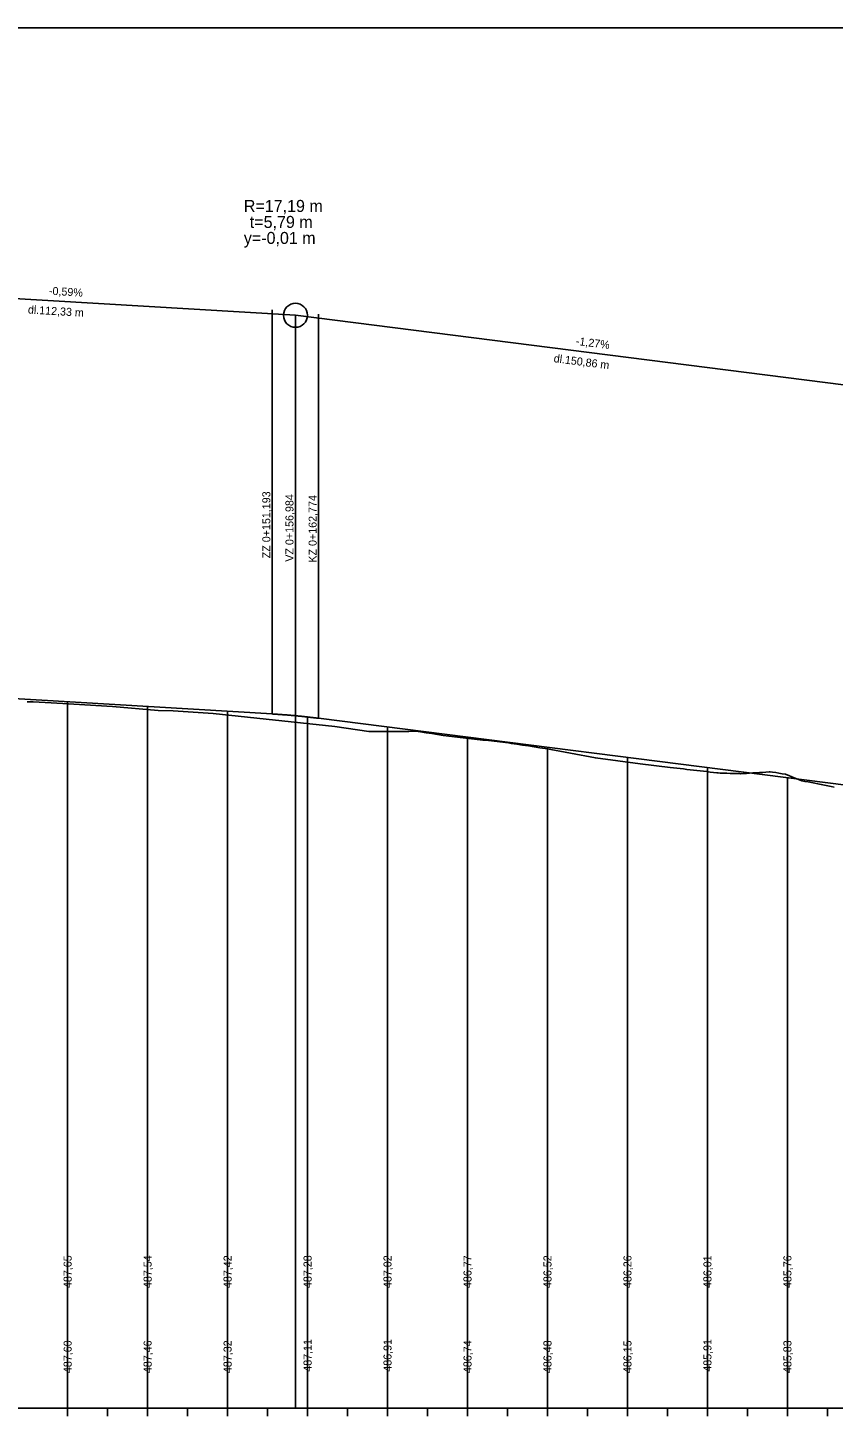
# Model space of a CAD drawing. Extents: x -632716 to -629545, y -1094726 to -1088285.
# Drawn here: x -632393.4 to -632192, y -1091019.7 to -1090670.2 of the extents above; entities that cross this region are included whole.
import ezdxf

# ---------------------------------------------------------------- set-up
doc = ezdxf.new("R2010")
doc.units = 0
for name, color, linetype in [('20', 7, 'Continuous'), ('Default', 7, 'Continuous'), ('formát', 7, 'Continuous'), ('NIVELETA_VYSKY', 7, 'Continuous'), ('REZ_TENKA', 7, 'Continuous'), ('REZ_TLUSTA', 7, 'Continuous'), ('SKLONY_NIVELETA', 7, 'Continuous'), ('SKLONY_POPIS', 7, 'Continuous'), ('TECNY_NIVELETA', 7, 'Continuous'), ('TEREN_VYSKY', 7, 'Continuous'), ('VOZOVKA', 7, 'Continuous')]:
    doc.layers.add(name, color=color, linetype=linetype)

msp = doc.modelspace()

# ---------------------------------------------------------------- linework, layer by layer
at = {"layer": '20'}
for points in [[(-632383.46, -1090838.65), (-632383.46, -1090965.2), (-632383.46, -1091015.2), (-632383.46, -1090955.2)], [(-632363.46, -1090839.84), (-632363.46, -1090965.2), (-632363.46, -1091015.2), (-632363.46, -1090955.2)], [(-632343.46, -1090841.03), (-632343.46, -1090965.2), (-632343.46, -1091015.2), (-632343.46, -1090955.2)], [(-632323.46, -1090842.44), (-632323.46, -1090965.2), (-632323.46, -1091015.2), (-632323.46, -1090955.2)], [(-632303.46, -1090844.95), (-632303.46, -1090965.2), (-632303.46, -1091015.2), (-632303.46, -1090955.2)], [(-632283.46, -1090847.49), (-632283.46, -1090965.2), (-632283.46, -1091015.2), (-632283.46, -1090955.2)], [(-632263.46, -1090850.03), (-632263.46, -1090965.2), (-632263.46, -1091015.2), (-632263.46, -1090955.2)], [(-632243.46, -1090852.56), (-632243.46, -1090965.2), (-632243.46, -1091015.2), (-632243.46, -1090955.2)], [(-632223.46, -1090855.1), (-632223.46, -1090965.2), (-632223.46, -1091015.2), (-632223.46, -1090955.2)], [(-632203.46, -1090857.64), (-632203.46, -1090965.2), (-632203.46, -1091015.2), (-632203.46, -1090955.2)]]:
    msp.add_lwpolyline(points, dxfattribs=at)
at = {"layer": 'Default'}
for p, q in [((-632412.05, -1090836.95), (-632332.27, -1090841.69)), ((-632412.05, -1090836.95), (-632332.27, -1090841.69)), ((-632320.69, -1090842.77), (-632188.1, -1090859.58)), ((-632320.69, -1090842.77), (-632188.1, -1090859.58))]:
    msp.add_line(p, q, dxfattribs=at)
msp.add_lwpolyline([(-632332.27, -1090841.69), (-632332.03, -1090841.71), (-632331.79, -1090841.72), (-632331.55, -1090841.74), (-632331.31, -1090841.75), (-632331.06, -1090841.77), (-632330.82, -1090841.78), (-632330.58, -1090841.8), (-632330.34, -1090841.82), (-632330.1, -1090841.83), (-632329.86, -1090841.85), (-632329.62, -1090841.87), (-632329.38, -1090841.89), (-632329.13, -1090841.91), (-632328.89, -1090841.92), (-632328.65, -1090841.94), (-632328.41, -1090841.96), (-632328.17, -1090841.98), (-632327.93, -1090842), (-632327.69, -1090842.02), (-632327.45, -1090842.05), (-632327.2, -1090842.07), (-632326.96, -1090842.09), (-632326.72, -1090842.11), (-632326.24, -1090842.15), (-632326, -1090842.18), (-632325.76, -1090842.2), (-632325.52, -1090842.22), (-632325.27, -1090842.25), (-632325.03, -1090842.27), (-632324.79, -1090842.3), (-632324.55, -1090842.32), (-632324.31, -1090842.35), (-632324.07, -1090842.37), (-632323.83, -1090842.4), (-632323.58, -1090842.43), (-632323.34, -1090842.45), (-632323.1, -1090842.48), (-632322.86, -1090842.51), (-632322.62, -1090842.54), (-632322.38, -1090842.56), (-632322.14, -1090842.59), (-632321.9, -1090842.62), (-632321.65, -1090842.65), (-632321.41, -1090842.68), (-632321.17, -1090842.71), (-632320.93, -1090842.74), (-632320.69, -1090842.77)], dxfattribs=at)
msp.add_lwpolyline([(-632332.27, -1090841.69), (-632332.03, -1090841.71), (-632331.79, -1090841.72), (-632331.55, -1090841.74), (-632331.31, -1090841.75), (-632331.06, -1090841.77), (-632330.82, -1090841.78), (-632330.58, -1090841.8), (-632330.34, -1090841.82), (-632330.1, -1090841.83), (-632329.86, -1090841.85), (-632329.62, -1090841.87), (-632329.38, -1090841.89), (-632329.13, -1090841.91), (-632328.89, -1090841.92), (-632328.65, -1090841.94), (-632328.41, -1090841.96), (-632328.17, -1090841.98), (-632327.93, -1090842), (-632327.69, -1090842.02), (-632327.45, -1090842.05), (-632327.2, -1090842.07), (-632326.96, -1090842.09), (-632326.72, -1090842.11), (-632326.24, -1090842.15), (-632326, -1090842.18), (-632325.76, -1090842.2), (-632325.52, -1090842.22), (-632325.27, -1090842.25), (-632325.03, -1090842.27), (-632324.79, -1090842.3), (-632324.55, -1090842.32), (-632324.31, -1090842.35), (-632324.07, -1090842.37), (-632323.83, -1090842.4), (-632323.58, -1090842.43), (-632323.34, -1090842.45), (-632323.1, -1090842.48), (-632322.86, -1090842.51), (-632322.62, -1090842.54), (-632322.38, -1090842.56), (-632322.14, -1090842.59), (-632321.9, -1090842.62), (-632321.65, -1090842.65), (-632321.41, -1090842.68), (-632321.17, -1090842.71), (-632320.93, -1090842.74), (-632320.69, -1090842.77)], dxfattribs=at)
at = {"layer": 'formát'}
msp.add_lwpolyline([(-632585.29, -1091264.2), (-630730.3, -1091264.2), (-630730.3, -1090670.2), (-632585.29, -1090670.2)], close=True, dxfattribs=at)
at = {"layer": 'REZ_TENKA'}
for p, q in [((-632373.46, -1091017.2), (-632373.46, -1091015.2)), ((-632363.46, -1091017.2), (-632363.46, -1091015.2)), ((-632353.46, -1091017.2), (-632353.46, -1091015.2)), ((-632343.46, -1091017.2), (-632343.46, -1091015.2)), ((-632333.46, -1091017.2), (-632333.46, -1091015.2)), ((-632323.46, -1091017.2), (-632323.46, -1091015.2)), ((-632313.46, -1091017.2), (-632313.46, -1091015.2)), ((-632303.46, -1091017.2), (-632303.46, -1091015.2)), ((-632293.46, -1091017.2), (-632293.46, -1091015.2)), ((-632273.46, -1091017.2), (-632273.46, -1091015.2)), ((-632263.46, -1091017.2), (-632263.46, -1091015.2)), ((-632253.46, -1091017.2), (-632253.46, -1091015.2)), ((-632243.46, -1091017.2), (-632243.46, -1091015.2)), ((-632233.46, -1091017.2), (-632233.46, -1091015.2)), ((-632223.46, -1091017.2), (-632223.46, -1091015.2)), ((-632213.46, -1091017.2), (-632213.46, -1091015.2)), ((-632203.46, -1091017.2), (-632203.46, -1091015.2)), ((-632193.46, -1091017.2), (-632193.46, -1091015.2))]:
    msp.add_line(p, q, dxfattribs=at)
at = {"layer": 'REZ_TLUSTA'}
for p, q in [((-632483.46, -1091015.2), (-630763.46, -1091015.2)), ((-632383.46, -1091017.2), (-632383.46, -1091013.2)), ((-632283.46, -1091017.2), (-632283.46, -1091013.2))]:
    msp.add_line(p, q, dxfattribs=at)
at = {"layer": 'SKLONY_NIVELETA'}
for p, q in [((-632438.81, -1090735.36), (-632326.48, -1090742.03)), ((-632326.48, -1090742.03), (-632326.48, -1091015.2)), ((-632326.48, -1090742.03), (-632175.62, -1090761.17)), ((-632412.05, -1090836.95), (-632332.27, -1090841.69)), ((-632320.69, -1090842.77), (-632188.1, -1090859.58))]:
    msp.add_line(p, q, dxfattribs=at)
msp.add_lwpolyline([(-632332.27, -1090841.69), (-632332.03, -1090841.71), (-632331.79, -1090841.72), (-632331.55, -1090841.74), (-632331.31, -1090841.75), (-632331.06, -1090841.77), (-632330.82, -1090841.78), (-632330.58, -1090841.8), (-632330.34, -1090841.82), (-632330.1, -1090841.83), (-632329.86, -1090841.85), (-632329.62, -1090841.87), (-632329.38, -1090841.89), (-632329.13, -1090841.91), (-632328.89, -1090841.92), (-632328.65, -1090841.94), (-632328.41, -1090841.96), (-632328.17, -1090841.98), (-632327.93, -1090842), (-632327.69, -1090842.02), (-632327.45, -1090842.05), (-632327.2, -1090842.07), (-632326.96, -1090842.09), (-632326.72, -1090842.11), (-632326.24, -1090842.15), (-632326, -1090842.18), (-632325.76, -1090842.2), (-632325.52, -1090842.22), (-632325.27, -1090842.25), (-632325.03, -1090842.27), (-632324.79, -1090842.3), (-632324.55, -1090842.32), (-632324.31, -1090842.35), (-632324.07, -1090842.37), (-632323.83, -1090842.4), (-632323.58, -1090842.43), (-632323.34, -1090842.45), (-632323.1, -1090842.48), (-632322.86, -1090842.51), (-632322.62, -1090842.54), (-632322.38, -1090842.56), (-632322.14, -1090842.59), (-632321.9, -1090842.62), (-632321.65, -1090842.65), (-632321.41, -1090842.68), (-632321.17, -1090842.71), (-632320.93, -1090842.74), (-632320.69, -1090842.77)], dxfattribs=at)
msp.add_circle((-632326.48, -1090742.03), 3, dxfattribs=at)
at = {"layer": 'TECNY_NIVELETA'}
for p, q in [((-632332.27, -1090841.69), (-632332.27, -1090740.69)), ((-632326.48, -1090742.03), (-632326.48, -1090742.03)), ((-632320.69, -1090842.77), (-632320.69, -1090741.77))]:
    msp.add_line(p, q, dxfattribs=at)
at = {"layer": 'VOZOVKA'}
msp.add_lwpolyline([(-632393.56, -1090838.66), (-632393.1, -1090838.65), (-632392.96, -1090838.65), (-632392.07, -1090838.69), (-632390.58, -1090838.77), (-632389.1, -1090838.86), (-632387.61, -1090838.94), (-632386.13, -1090839.02), (-632384.64, -1090839.1), (-632372.22, -1090839.79), (-632360.82, -1090840.81), (-632357.08, -1090840.92), (-632347.06, -1090841.56), (-632316.67, -1090844.86), (-632308.12, -1090846.09), (-632302.35, -1090846.1), (-632301.8, -1090846.1), (-632300.93, -1090846.09), (-632299.51, -1090846.06), (-632298.09, -1090846.03), (-632296.67, -1090846), (-632296.41, -1090846), (-632295.25, -1090846.17), (-632293.83, -1090846.39), (-632292.4, -1090846.6), (-632290.98, -1090846.82), (-632289.56, -1090847.04), (-632288.81, -1090847.16), (-632288.14, -1090847.23), (-632286.72, -1090847.39), (-632285.3, -1090847.55), (-632283.88, -1090847.72), (-632282.46, -1090847.88), (-632281.04, -1090848.04), (-632279.61, -1090848.2), (-632278.19, -1090848.36), (-632276.77, -1090848.52), (-632275.35, -1090848.69), (-632273.93, -1090848.85), (-632273.19, -1090848.93), (-632272.51, -1090849.04), (-632271.09, -1090849.26), (-632269.67, -1090849.47), (-632268.24, -1090849.69), (-632266.82, -1090849.91), (-632265.4, -1090850.12), (-632264.06, -1090850.33), (-632263.98, -1090850.34), (-632251.47, -1090852.68), (-632240.25, -1090854.16), (-632232.78, -1090855.04), (-632231.94, -1090855.14), (-632231.11, -1090855.24), (-632230.28, -1090855.33), (-632229.44, -1090855.43), (-632228.61, -1090855.53), (-632227.78, -1090855.63), (-632226.94, -1090855.72), (-632226.11, -1090855.82), (-632225.28, -1090855.92), (-632224.44, -1090856.01), (-632223.61, -1090856.11), (-632222.78, -1090856.21), (-632221.94, -1090856.3), (-632221.11, -1090856.4), (-632220.79, -1090856.43), (-632220.28, -1090856.46), (-632219.44, -1090856.49), (-632218.61, -1090856.52), (-632217.78, -1090856.55), (-632216.96, -1090856.58), (-632216.56, -1090856.59), (-632216.15, -1090856.6), (-632215.34, -1090856.61), (-632215.13, -1090856.62), (-632214.52, -1090856.58), (-632213.71, -1090856.54), (-632212.9, -1090856.49), (-632212.08, -1090856.44), (-632211.27, -1090856.39), (-632210.46, -1090856.33), (-632209.64, -1090856.28), (-632208.83, -1090856.22), (-632208.02, -1090856.17), (-632207.76, -1090856.15), (-632207.2, -1090856.24), (-632206.39, -1090856.36), (-632205.58, -1090856.49), (-632204.76, -1090856.62), (-632203.95, -1090856.75), (-632203.77, -1090856.78), (-632203.14, -1090857.05), (-632202.32, -1090857.39), (-632201.51, -1090857.73), (-632200.7, -1090858.08), (-632200.03, -1090858.36), (-632199.88, -1090858.39), (-632199.07, -1090858.53), (-632198.26, -1090858.67), (-632197.44, -1090858.82), (-632196.63, -1090858.97), (-632195.82, -1090859.13), (-632195, -1090859.29), (-632194.19, -1090859.45), (-632193.38, -1090859.62), (-632192.56, -1090859.8), (-632191.75, -1090859.97)], dxfattribs=at)

# ---------------------------------------------------------------- texts
at = {"layer": 'NIVELETA_VYSKY'}
for s, p in [('487,65', (-632382.46, -1090985.2)), ('487,54', (-632362.46, -1090985.2)), ('487,42', (-632342.46, -1090985.2)), ('487,28', (-632322.46, -1090985.2)), ('487,02', (-632302.46, -1090985.2)), ('486,77', (-632282.46, -1090985.2)), ('486,52', (-632262.46, -1090985.2)), ('486,26', (-632242.46, -1090985.2)), ('486,01', (-632222.46, -1090985.2)), ('485,76', (-632202.46, -1090985.2))]:
    msp.add_text(s, height=2, rotation=90, dxfattribs=at).set_placement(p)
at = {"layer": 'SKLONY_POPIS'}
for s, p in [('R=17,19 m', (-632339.39, -1090716.19)), ('t=5,79 m', (-632337.9, -1090720.19)), ('y=-0,01 m', (-632339.39, -1090724.19))]:
    msp.add_text(s, height=3, dxfattribs=at).set_placement(p)
for s, rotation, p in [('-0,59%', 356.5987, (-632388.17, -1090736.87)), ('dl.112,33 m', 356.5987, (-632393.42, -1090741.56)), ('-1,27%', 352.7722, (-632256.44, -1090749.4)), ('dl.150,86 m', 352.7722, (-632261.99, -1090753.74)), ('ZZ 0+151,193', 90, (-632332.77, -1090802.77)), ('VZ 0+156,984', 90, (-632326.98, -1090803.62)), ('KZ 0+162,774', 90, (-632321.19, -1090803.85))]:
    msp.add_text(s, height=2, rotation=rotation, dxfattribs=at).set_placement(p)
at = {"layer": 'TEREN_VYSKY'}
for s, p in [('487,60', (-632382.46, -1091006.46)), ('487,46', (-632362.46, -1091006.46)), ('487,32', (-632342.46, -1091006.46)), ('487,11', (-632322.46, -1091006.12)), ('486,91', (-632302.46, -1091006.12)), ('486,74', (-632282.46, -1091006.46)), ('486,48', (-632262.46, -1091006.46)), ('486,15', (-632242.46, -1091006.46)), ('485,91', (-632222.46, -1091006.12)), ('485,83', (-632202.46, -1091006.46))]:
    msp.add_text(s, height=2, rotation=90, dxfattribs=at).set_placement(p)

doc.saveas('drawing.dxf')
